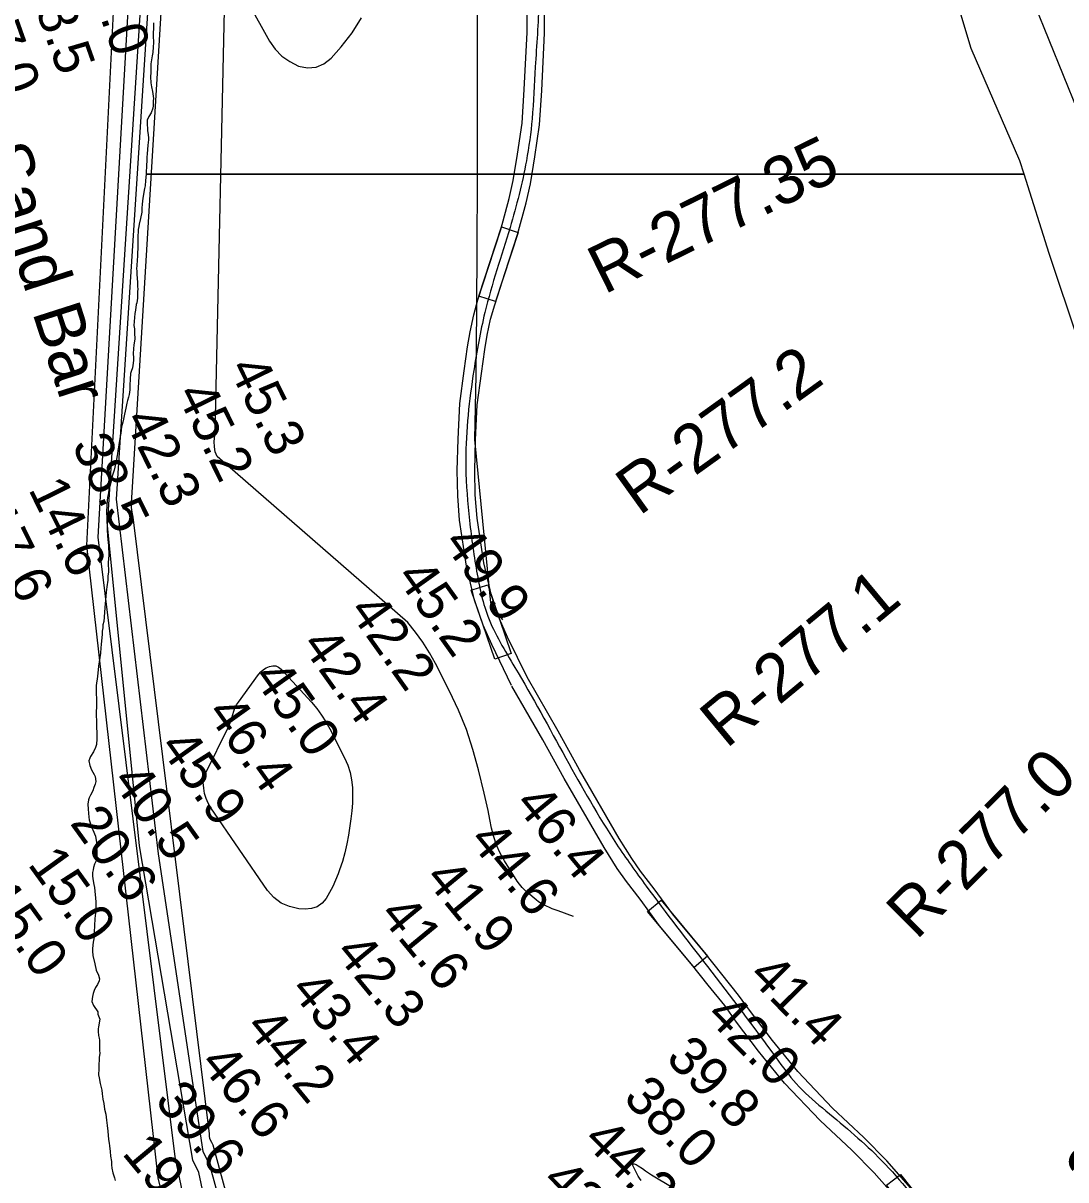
# Model space of a CAD drawing. Extents: x 3187622 to 3225504, y 800805 to 826213.
# Drawn here: x 3200146 to 3201935, y 818665 to 820650 of the extents above; entities that cross this region are included whole.
import ezdxf

# ---------------------------------------------------------------- set-up
doc = ezdxf.new("R2010")
doc.units = 0
for name, color, linetype in [('V-RIVR-IDEN', 7, 'Continuous'), ('V-RIVR-RANG', 7, 'Continuous'), ('V-RIVR-RANG-IDEN', 7, 'Continuous'), ('V-ROAD-CNTR', 7, 'Continuous'), ('V-SITE-VEGE', 7, 'Continuous'), ('V-TOPO-DPTH', 7, 'Continuous'), ('V-TOPO-MAJR', 7, 'Continuous'), ('V-TOPO-MINR', 7, 'Continuous')]:
    doc.layers.add(name, color=color, linetype=linetype)

msp = doc.modelspace()

# ---------------------------------------------------------------- linework, layer by layer
at = {"layer": 'V-ROAD-CNTR'}
for points in [[(3200984.6, 819513.3), (3200950.4, 819583.5), (3200935.7, 819616.7), (3200921.1, 819659.6), (3200907.2, 819718.2), (3200895.4, 819797), (3200892.1, 819839), (3200891.4, 819882), (3200892.6, 819935.8), (3200895.6, 819997.4), (3200903, 820053), (3200909.1, 820094.5), (3200913.2, 820120.2), (3200919.5, 820149.3), (3200926.8, 820175.2), (3200944.9, 820231.2), (3200966, 820295.8), (3200980.5, 820348.9), (3200987.3, 820380), (3200994.9, 820425), (3201002.6, 820478.2), (3201006.2, 820536.1), (3201011, 820633.6), (3201011.2, 820683.1)], [(3201011.6, 819526.5), (3200977.6, 819596.1), (3200963.7, 819627.6), (3200950, 819667.9), (3200936.7, 819723.9), (3200925.2, 819800.4), (3200922.1, 819840.4), (3200921.4, 819881.9), (3200922.6, 819934.8), (3200925.5, 819994.7), (3200932.7, 820048.8), (3200938.7, 820090), (3200942.7, 820114.6), (3200948.6, 820142.1), (3200955.5, 820166.6), (3200973.4, 820221.9), (3200994.7, 820287.2), (3201009.6, 820341.7), (3201016.8, 820374.2), (3201024.5, 820420.4), (3201032.4, 820475.1), (3201036.2, 820534.4), (3201041, 820632.8), (3201041.2, 820683.5)], [(3201677.6, 818641.7), (3201628.6, 818697.8), (3201589, 818737.6), (3201535.1, 818788), (3201475.4, 818850.9), (3201432, 818904.4), (3201394.6, 818953.8), (3201374, 818982.2), (3201345.2, 819018), (3201316.4, 819054.1), (3201262.1, 819119.3), (3201229.1, 819164.5), (3201205.9, 819194.8), (3201190.7, 819216.2), (3201168.9, 819250.7), (3201101.1, 819368.5), (3201064.4, 819435.1), (3201011.1, 819527.4)], [(3201654.5, 818622.5), (3201606.6, 818677.4), (3201568.2, 818716), (3201513.9, 818766.7), (3201452.9, 818831.1), (3201408.4, 818885.9), (3201370.5, 818935.9), (3201350.2, 818964), (3201321.8, 818999.3), (3201293.1, 819035.2), (3201238.4, 819100.9), (3201205.1, 819146.6), (3201181.8, 819177), (3201165.7, 819199.5), (3201143.2, 819235.2), (3201075, 819353.8), (3201038.3, 819420.3), (3200985.1, 819512.4)]]:
    msp.add_lwpolyline(points, dxfattribs=at)
for points in [[(3200928.6, 820181.3), (3200967.4, 820300.2), (3200995.9, 820290.9), (3200957.1, 820172)], [(3200955.5, 819558.3), (3200915.3, 819676.7), (3200943.7, 819686.3), (3200983.9, 819568)], [(3201297.8, 819029.5), (3201217.8, 819125.6), (3201240.9, 819144.8), (3201320.9, 819048.7)], [(3201705.8, 818558), (3201628, 818655.8), (3201651.5, 818674.5), (3201729.3, 818576.6)]]:
    msp.add_lwpolyline(points, close=True, dxfattribs=at)
msp.add_spline([(3201024.1, 823274.7), (3201018, 823194.2), (3201004.7, 822963.7), (3200987.4, 822858.7), (3200966.9, 822788.4), (3200937.8, 822670.8), (3200879.4, 822446.8), (3200861.2, 822331.3), (3200852.3, 822205.9), (3200846, 822103), (3200850.5, 822002.7), (3200859.8, 821900.4), (3200873.1, 821709.1), (3200906.2, 821470.9), (3200956.6, 821171.3), (3200981.8, 821020.5), (3201004.4, 820882.9), (3201024.9, 820767.6), (3201030.7, 820687.4), (3201025.1, 820574.8), (3201019.7, 820485.6), (3201009.9, 820413.7), (3200981.8, 820299.2), (3200938.6, 820153.1), (3200919.7, 820054.1), (3200905.9, 819899.8), (3200911.1, 819808), (3200923.6, 819715), (3200943.7, 819632.5), (3200990, 819544.5), (3201077.6, 819388.7), (3201164.6, 819241.3), (3201215.4, 819169.2), (3201320.5, 819031.2), (3201438.3, 818874.6), (3201472.9, 818830.2), (3201517.8, 818788.5), (3201613.7, 818704.1), (3201703.7, 818596), (3201763.8, 818510.5), (3201836.1, 818397.9), (3201893.8, 818288.1), (3201910, 818246.3), (3201920.9, 818198.1), (3201929.8, 818155.8), (3201937.9, 818094.1), (3201957.7, 817998.6), (3201977.9, 817926.4), (3202055.4, 817776.5), (3202147, 817624), (3202184.4, 817575.3), (3202228.3, 817509.6), (3202265.9, 817465), (3202335.4, 817389.3), (3202595.4, 817156.1), (3202698.6, 817066.2), (3202845.2, 816933.8), (3202967.2, 816832.3), (3203084.1, 816744.2), (3203205.8, 816662.3), (3203334.5, 816585.9), (3203420.1, 816528.7), (3203529.1, 816448.4), (3203624.3, 816386.4), (3203720.3, 816332.5), (3203800.7, 816304.6), (3203929.1, 816241.3), (3204015.1, 816192.4), (3204112.5, 816105.4), (3204200.5, 816023.3)], degree=3, dxfattribs=at)
at = {"layer": 'V-SITE-VEGE'}
for p, q in [((3201772.9, 820606.3), (3201722.7, 820773.7)), ((3201881.7, 820681.6), (3201999.6, 820390.6)), ((3200370.4, 820650.2), (3200370.4, 820645)), ((3200370.4, 820645), (3200369.7, 820628.8)), ((3200369.9, 820615.9), (3200369.5, 820609)), ((3200369.7, 820628.8), (3200369.9, 820615.9)), ((3200368.1, 820594), (3200365.8, 820580.3)), ((3200368.8, 820599.3), (3200368.1, 820594)), ((3200369.5, 820609), (3200368.8, 820599.3)), ((3201856.6, 820413.7), (3201772.9, 820606.3)), ((3200365.8, 820580.3), (3200365.4, 820573.4)), ((3200365.4, 820573.4), (3200365.5, 820564.9)), ((3200365.5, 820564.9), (3200365.2, 820557.6)), ((3200365.2, 820557.6), (3200365.7, 820547.5)), ((3200365.7, 820547.5), (3200366.5, 820540.6)), ((3200366.5, 820540.6), (3200368.2, 820532.6)), ((3200368.2, 820532.6), (3200370, 820520.5)), ((3200370, 820520.5), (3200369.6, 820516.4)), ((3200369.6, 820516.4), (3200369.7, 820507.9)), ((3200366.2, 820495.8), (3200362.2, 820489.7)), ((3200368.9, 820503.9), (3200366.2, 820495.8)), ((3200369.7, 820507.9), (3200368.9, 820503.9)), ((3200362.2, 820489.7), (3200359.4, 820483.2)), ((3200359.4, 820483.2), (3200359.4, 820479.1)), ((3200359.4, 820479.1), (3200360, 820465.8)), ((3200360, 820465.8), (3200360.9, 820458.1)), ((3200360.9, 820458.1), (3200361.7, 820452.9)), ((3200361.7, 820452.9), (3200361.7, 820449.6)), ((3200360.6, 820440.7), (3200359.1, 820425.8)), ((3200361.7, 820449.6), (3200360.6, 820440.7)), ((3200358.8, 820414), (3200358.1, 820405.5)), ((3200359.1, 820425.8), (3200358.8, 820419.7)), ((3200358.8, 820419.7), (3200358.8, 820414)), ((3201863.9, 820390.6), (3201856.6, 820413.7)), ((3200357.8, 820393), (3200357.6, 820390.6)), ((3200358.1, 820405.5), (3200357.8, 820393)), ((3200357.6, 820390.6), (3201863.9, 820390.6))]:
    msp.add_line(p, q, dxfattribs=at)
for points in [[(3200357.6, 820390.6), (3200356.3, 820379.7), (3200355.6, 820370.8), (3200354.9, 820365.9), (3200351.8, 820349.7), (3200351.4, 820344.4), (3200350.7, 820339.2), (3200350.3, 820332.3), (3200350.4, 820325.8), (3200348.1, 820314.5), (3200345.7, 820305.2), (3200345, 820300.7), (3200343.8, 820295.8), (3200343.8, 820292.2), (3200343.1, 820284.1), (3200343.3, 820263.9), (3200342.6, 820255), (3200342.6, 820249.8), (3200341.9, 820242.9), (3200341.5, 820234), (3200341.2, 820228.3), (3200341.6, 820225.1), (3200341.7, 820218.6), (3200342.6, 820205.3), (3200342.7, 820198), (3200343.1, 820193.6), (3200342.8, 820189.5), (3200342.9, 820177.8), (3200342.1, 820174.2), (3200341.7, 820170.1), (3200340.6, 820166.9), (3200339, 820157.6), (3200337.9, 820151.5), (3200336.5, 820130.8), (3200337.3, 820125.2), (3200337.8, 820118.7), (3200337.9, 820107.8), (3200336.4, 820098.1), (3200335.6, 820090.8), (3200335.3, 820083.1), (3200335.8, 820075.5), (3200335.8, 820071.4), (3200335.4, 820066.6), (3200333.9, 820058.5), (3200331.9, 820052), (3200330.8, 820048.7), (3200330.8, 820045.5), (3200330.4, 820042.3), (3200330.1, 820036.2), (3200329.3, 820031.3), (3200329.4, 820024.1), (3200329.8, 820020.4), (3200328.3, 820012.7), (3200327.5, 820008.3), (3200325.5, 820002.2), (3200324.4, 819997.7), (3200322.4, 819989.2), (3200320.5, 819979.1), (3200318.6, 819970.6), (3200317.8, 819965.3), (3200315.5, 819957.2), (3200313.9, 819946.3), (3200312.4, 819937), (3200310.5, 819926.4), (3200310.1, 819922.4), (3200309, 819916.3), (3200308.2, 819910.7), (3200305.9, 819898.9), (3200303.6, 819888), (3200302.4, 819883.1), (3200299.3, 819872.6), (3200297, 819861.6), (3200293.8, 819849.1), (3200293.1, 819844.2), (3200291.5, 819835.7), (3200290.8, 819830.5), (3200290, 819823.2), (3200289.8, 819811), (3200289.9, 819800.5), (3200290.3, 819793.3), (3200290.8, 819788.4), (3200290.8, 819781.5), (3200291.4, 819769.8), (3200292.3, 819758.9), (3200293.1, 819753.3), (3200293.3, 819737.1), (3200292.6, 819724.2), (3200292.7, 819708.4), (3200292, 819701.1), (3200291.7, 819694.2), (3200290.2, 819682.9), (3200289, 819673.2), (3200287.9, 819659.8), (3200287.2, 819653.8), (3200286.9, 819647.3), (3200285.4, 819630.3), (3200284.7, 819623.4), (3200283.5, 819617.3), (3200283.1, 819612.1), (3200282, 819606.4), (3200282, 819601.2)], [(3201957, 820104), (3201906.8, 820254.7), (3201863.9, 820390.6), (3200357.6, 820390.6)], [(3200282, 819601.2), (3200280.2, 819583.8), (3200279.8, 819577.7), (3200279.1, 819568.8), (3200275.7, 819546.5), (3200273.8, 819528.7), (3200272, 819513.3), (3200272, 819506.5), (3200271.7, 819496.8), (3200272.1, 819493.5), (3200272.3, 819475.3), (3200272, 819469.3), (3200271.6, 819460.4), (3200272.1, 819454.3), (3200272.1, 819450.7), (3200272.6, 819444.2), (3200272.7, 819429.7), (3200273.2, 819422), (3200272.5, 819411.9), (3200270.9, 819407), (3200267, 819399.3), (3200262.2, 819391.6), (3200261, 819388.7), (3200259.4, 819383.9), (3200261.1, 819376.2), (3200264, 819368.5), (3200268.1, 819360.9), (3200270.2, 819357.3), (3200271.1, 819348.4), (3200270.3, 819344.3), (3200269.1, 819341.1), (3200267.9, 819338.3), (3200266, 819332.6), (3200262, 819325.3), (3200260, 819320.8), (3200258.8, 819317.1), (3200257.7, 819309.5), (3200257.8, 819301.4), (3200259.1, 819287.6), (3200260, 819282.8), (3200262.1, 819275.9), (3200262.9, 819272.3), (3200265.8, 819265.5), (3200270.8, 819254.6), (3200272.1, 819244.1), (3200272.1, 819237.6), (3200273, 819227.5), (3200273.1, 819223.9), (3200272.8, 819215), (3200270, 819209.3), (3200268.8, 819206.5), (3200267.2, 819201.2), (3200266.5, 819197.2), (3200265.7, 819192.3), (3200265.7, 819187), (3200266.2, 819181.4), (3200267.9, 819172.1), (3200269.2, 819166.9), (3200271.4, 819142.2), (3200271.5, 819136.2), (3200270.4, 819122.8), (3200269.3, 819113.5), (3200269, 819101), (3200268.3, 819090.8), (3200268.7, 819086.4), (3200268, 819078.7), (3200266.8, 819073), (3200265.3, 819062.1), (3200265.3, 819057.7), (3200266.2, 819050), (3200269.6, 819035.5), (3200271.7, 819025), (3200275.8, 819016.1), (3200277.5, 819010.1), (3200277.1, 819006.8), (3200274, 819000.3), (3200270.8, 818995.1), (3200268.4, 818989.8), (3200266.4, 818984.9), (3200265.3, 818979.6), (3200264.5, 818971.2), (3200267.4, 818964.3), (3200274.4, 818953.1), (3200274.9, 818949.4), (3200277.8, 818940.6), (3200275.9, 818927.6), (3200275.1, 818924), (3200275.1, 818919.5), (3200276, 818913), (3200276.9, 818908.2), (3200277.3, 818904.6), (3200277.5, 818887.2), (3200277.9, 818882.7), (3200277.2, 818875.1), (3200277.2, 818871), (3200276.5, 818862.9), (3200276.1, 818857.7), (3200276.2, 818852.4), (3200275.8, 818848.8), (3200275.8, 818845.1), (3200277.1, 818839.9)], [(3200277.1, 818839.9), (3200278.8, 818830.2), (3200281.3, 818818.9), (3200282.2, 818812.8), (3200282.7, 818808), (3200283.5, 818803.6), (3200284.8, 818795.9), (3200286.1, 818786.2), (3200288.2, 818777.7), (3200289.5, 818767.6), (3200290.4, 818758.4), (3200291.7, 818748.7), (3200293.1, 818734.1), (3200293.9, 818728.1), (3200294.4, 818723.2), (3200295.7, 818713.5), (3200296.6, 818705.5), (3200297.9, 818696.6), (3200297.9, 818690.9), (3200298.8, 818684.9), (3200300.5, 818677.2), (3200303.4, 818668.7), (3200304.6, 818663.9)]]:
    msp.add_lwpolyline(points, dxfattribs=at)
at = {"layer": 'V-TOPO-DPTH'}
msp.add_lwpolyline([(3200550.2, 817975), (3200378, 818668.8), (3200255.9, 819753.6), (3200302.9, 820692.1)], dxfattribs=at)
at = {"layer": 'V-TOPO-MAJR'}
msp.add_lwpolyline([(3200640.8, 818056), (3200466.3, 818692.7), (3200460.7, 818703), (3200455.2, 818713.5), (3200378.7, 819224.4), (3200306.5, 819832.8), (3200365.1, 820738.6)], dxfattribs=at)
at = {"layer": 'V-TOPO-MINR'}
for points in [[(3200969.6, 819625.9), (3200956.3, 819644.4), (3200948.9, 819655.2), (3200921.6, 819935.7), (3200923.5, 820046.2), (3200924.9, 820156.8), (3200925.7, 820267.4), (3200926.1, 820378), (3200926.2, 820846.4)], [(3201090.6, 819116.7), (3201064.3, 819126.5), (3201059.3, 819128.4), (3201054.4, 819130.3), (3201049.4, 819132.4), (3201044.5, 819134.5), (3201039.8, 819136.8), (3201035.2, 819139.4), (3201030.8, 819142.4), (3201026.5, 819145.6), (3201012.2, 819157.5), (3201007.1, 819162.1), (3201002.4, 819167), (3200998.2, 819172.3), (3200994.3, 819177.8), (3200972.2, 819212.6), (3200964.8, 819225.9), (3200958.5, 819239.5), (3200953.9, 819253.8), (3200950.2, 819268.6), (3200947.3, 819283.6), (3200944.3, 819298.6), (3200941, 819313.5), (3200937.5, 819328.4), (3200927.8, 819368.9), (3200918.1, 819403.6), (3200906.9, 819437.7), (3200893.2, 819470.9), (3200878, 819503.5), (3200853.7, 819551), (3200843.4, 819569.6), (3200832.3, 819587.6), (3200819.9, 819604.7), (3200806.7, 819621.4), (3200479.4, 819906.5), (3200476.1, 819914.5), (3200474.7, 819923), (3200474.4, 819931.9), (3200475.8, 819948), (3200493.4, 820750.7)], [(3200495.7, 820751.2), (3200569.2, 820619.2), (3200579, 820605.3), (3200590.3, 820593.2), (3200604, 820583.8), (3200619.1, 820576.1), (3200634.6, 820573.4), (3200649.2, 820574.2), (3200662.6, 820580.3), (3200675.1, 820589.9), (3200692.4, 820609.5), (3200710.9, 820633.5), (3200726.9, 820658.8)], [(3200635.3, 818124.9), (3200472.4, 818724.6), (3200471.2, 818726.8), (3200470.6, 818727.9), (3200470, 818729.1), (3200467.9, 818733.4), (3200466.9, 818735.9), (3200466.2, 818739.8), (3200466.1, 818743.8), (3200335.3, 819802.3), (3200333.3, 819810.5), (3200332.4, 819818.9), (3200332.2, 819827.4), (3200332.8, 819836), (3200333.7, 819844.5), (3200386.9, 820725.4)], [(3200550.2, 817975), (3200378, 818668.8), (3200255.9, 819753.6), (3200302.9, 820692.1)], [(3200546.3, 818039.1), (3200407.2, 818704.4), (3200275, 819768), (3200328, 820692.2)], [(3200577.7, 818065.6), (3200448.2, 818677.9), (3200437.6, 818698.8), (3200346.2, 819238.2), (3200291, 819787.9), (3200349.6, 820699.9)], [(3200455.2, 819355), (3200456.5, 819358), (3200458.2, 819360.8), (3200459.8, 819363.7), (3200498.4, 819441.1), (3200500.8, 819446.6), (3200503, 819452.1), (3200504.7, 819457.8), (3200506.2, 819463.5), (3200507.8, 819469.2), (3200509.9, 819474.7), (3200512.6, 819479.9), (3200515.8, 819484.9), (3200550.2, 819532.1), (3200554.2, 819536.6), (3200558.6, 819540.6), (3200563.7, 819543.7), (3200569.2, 819546.2), (3200574.7, 819547.1), (3200580, 819546.8), (3200584.7, 819544.6), (3200589.2, 819541.3), (3200641.2, 819484.6), (3200650.2, 819473.9), (3200658.6, 819462.7), (3200666.1, 819450.9), (3200672.9, 819438.7), (3200698.1, 819389), (3200703.4, 819376.8), (3200707.5, 819364.3), (3200710, 819351.3), (3200711.4, 819338.1), (3200711.6, 819324.7), (3200711.3, 819311.3), (3200710.2, 819298), (3200708.7, 819284.6), (3200704.7, 819256.5), (3200702, 819241.4), (3200698.7, 819226.4), (3200694.4, 819211.6), (3200689.5, 819197.1), (3200687, 819190.4), (3200682.6, 819179.4), (3200677.7, 819168.6), (3200672.3, 819158.1), (3200666.4, 819147.8), (3200659.3, 819139.7), (3200651.1, 819133.5), (3200641.3, 819130.5), (3200630.5, 819129.4), (3200619.6, 819130.3), (3200603.6, 819133.9), (3200589, 819139.9), (3200576.6, 819149.6), (3200565.5, 819161.8), (3200468.5, 819303.5), (3200464, 819311.3), (3200460.3, 819319.4), (3200457.9, 819328), (3200456.4, 819336.9), (3200455, 819351.9), (3200455.2, 819355)], [(3201206.6, 818664.1), (3201204.1, 818667.7), (3201201.8, 818671.6), (3201192.4, 818689.6), (3201192.3, 818690.8), (3201192.6, 818691.7), (3201193.4, 818692.3), (3201194.6, 818692.5), (3201198.4, 818691.4), (3201200.2, 818690.5), (3201201.9, 818689.4), (3201208.9, 818684.3), (3201214, 818680.6), (3201219.3, 818677), (3201224.7, 818673.5), (3201230.1, 818670.2), (3201329.2, 818611.4)]]:
    msp.add_lwpolyline(points, dxfattribs=at)

# ---------------------------------------------------------------- texts
at = {"layer": 'V-RIVR-IDEN'}
msp.add_text('Sand Bar', height=83, rotation=287.7909, dxfattribs=at).set_placement((3200073.2, 820430.3))
at = {"layer": 'V-RIVR-RANG'}
for s, rotation, p in [('19.0', 289.5507, (3200245.5, 820753)), ('18.5', 289.5507, (3200150.7, 820721.2)), ('17.0', 289.5507, (3200057, 820686.3)), ('45.3', 296.1083, (3200498.2, 820058.5)), ('45.2', 296.1083, (3200408.6, 820014.3)), ('42.3', 296.1083, (3200318.9, 819970.1)), ('38.5', 296.1083, (3200229.2, 819925.8)), ('14.6', 296.2369, (3200154.6, 819850.4)), ('17.6', 296.2369, (3200064.6, 819806.7)), ('49.9', 305.5583, (3200865.7, 819758.1)), ('45.2', 305.5583, (3200784.7, 819699.5)), ('42.2', 305.5583, (3200703.4, 819641.2)), ('42.4', 305.5583, (3200622.2, 819582.8)), ('45.0', 305.5583, (3200539.3, 819526.8)), ('46.4', 305.5583, (3200459.8, 819466.1)), ('45.9', 305.5583, (3200378.5, 819408)), ('40.5', 305.5583, (3200297.4, 819349.4)), ('46.4', 309.4983, (3200987.8, 819309.1)), ('20.6', 305.8361, (3200225.5, 819277.1)), ('44.6', 309.4983, (3200909.6, 819246.7)), ('15.0', 305.8361, (3200153.1, 819206.6)), ('41.9', 309.4983, (3200833.6, 819181.7)), ('15.0', 305.8361, (3200071.9, 819148.2)), ('41.6', 309.4983, (3200755.6, 819119.1)), ('42.3', 309.4983, (3200679.8, 819053.9)), ('41.4', 314.6583, (3201388.9, 819012.7)), ('43.4', 309.4983, (3200602.8, 818990.1)), ('42.0', 314.6583, (3201315.9, 818944.3)), ('44.2', 309.4983, (3200525.8, 818926.3)), ('39.8', 314.6583, (3201247, 818871.8)), ('46.6', 309.4983, (3200447.6, 818863.9)), ('39.6', 309.4983, (3200370.6, 818800.1)), ('38.0', 314.6583, (3201174, 818803.4)), ('44.2', 314.6583, (3201105.1, 818730.8)), ('19.3', 309.7615, (3200314.5, 818710.3)), ('43.2', 314.6583, (3201034.1, 818660.4))]:
    msp.add_text(s, height=67, rotation=rotation, dxfattribs=at).set_placement(p)
at = {"layer": 'V-RIVR-RANG-IDEN'}
for s, rotation, p in [('R-277.35', 26.25, (3201143.4, 820183.7)), ('R-277.2', 35.6986, (3201203.4, 819803.4)), ('R-277.1', 39.6416, (3201352.9, 819403.8)), ('R-277.0', 44.7992, (3201678.9, 819075.2)), ('R-276.95', 47.3527, (3201909.4, 818547.4))]:
    msp.add_text(s, height=83, rotation=rotation, dxfattribs=at).set_placement(p)

doc.saveas('drawing.dxf')
